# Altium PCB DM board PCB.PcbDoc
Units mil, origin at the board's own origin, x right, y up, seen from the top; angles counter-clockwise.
Board outline 3005.33 x 2700 mil, 4 copper layers (Top Layer, InternalPlane1, InternalPlane2, Bottom Layer); 39 components, 28 nets, 361 pads, 4 vias.
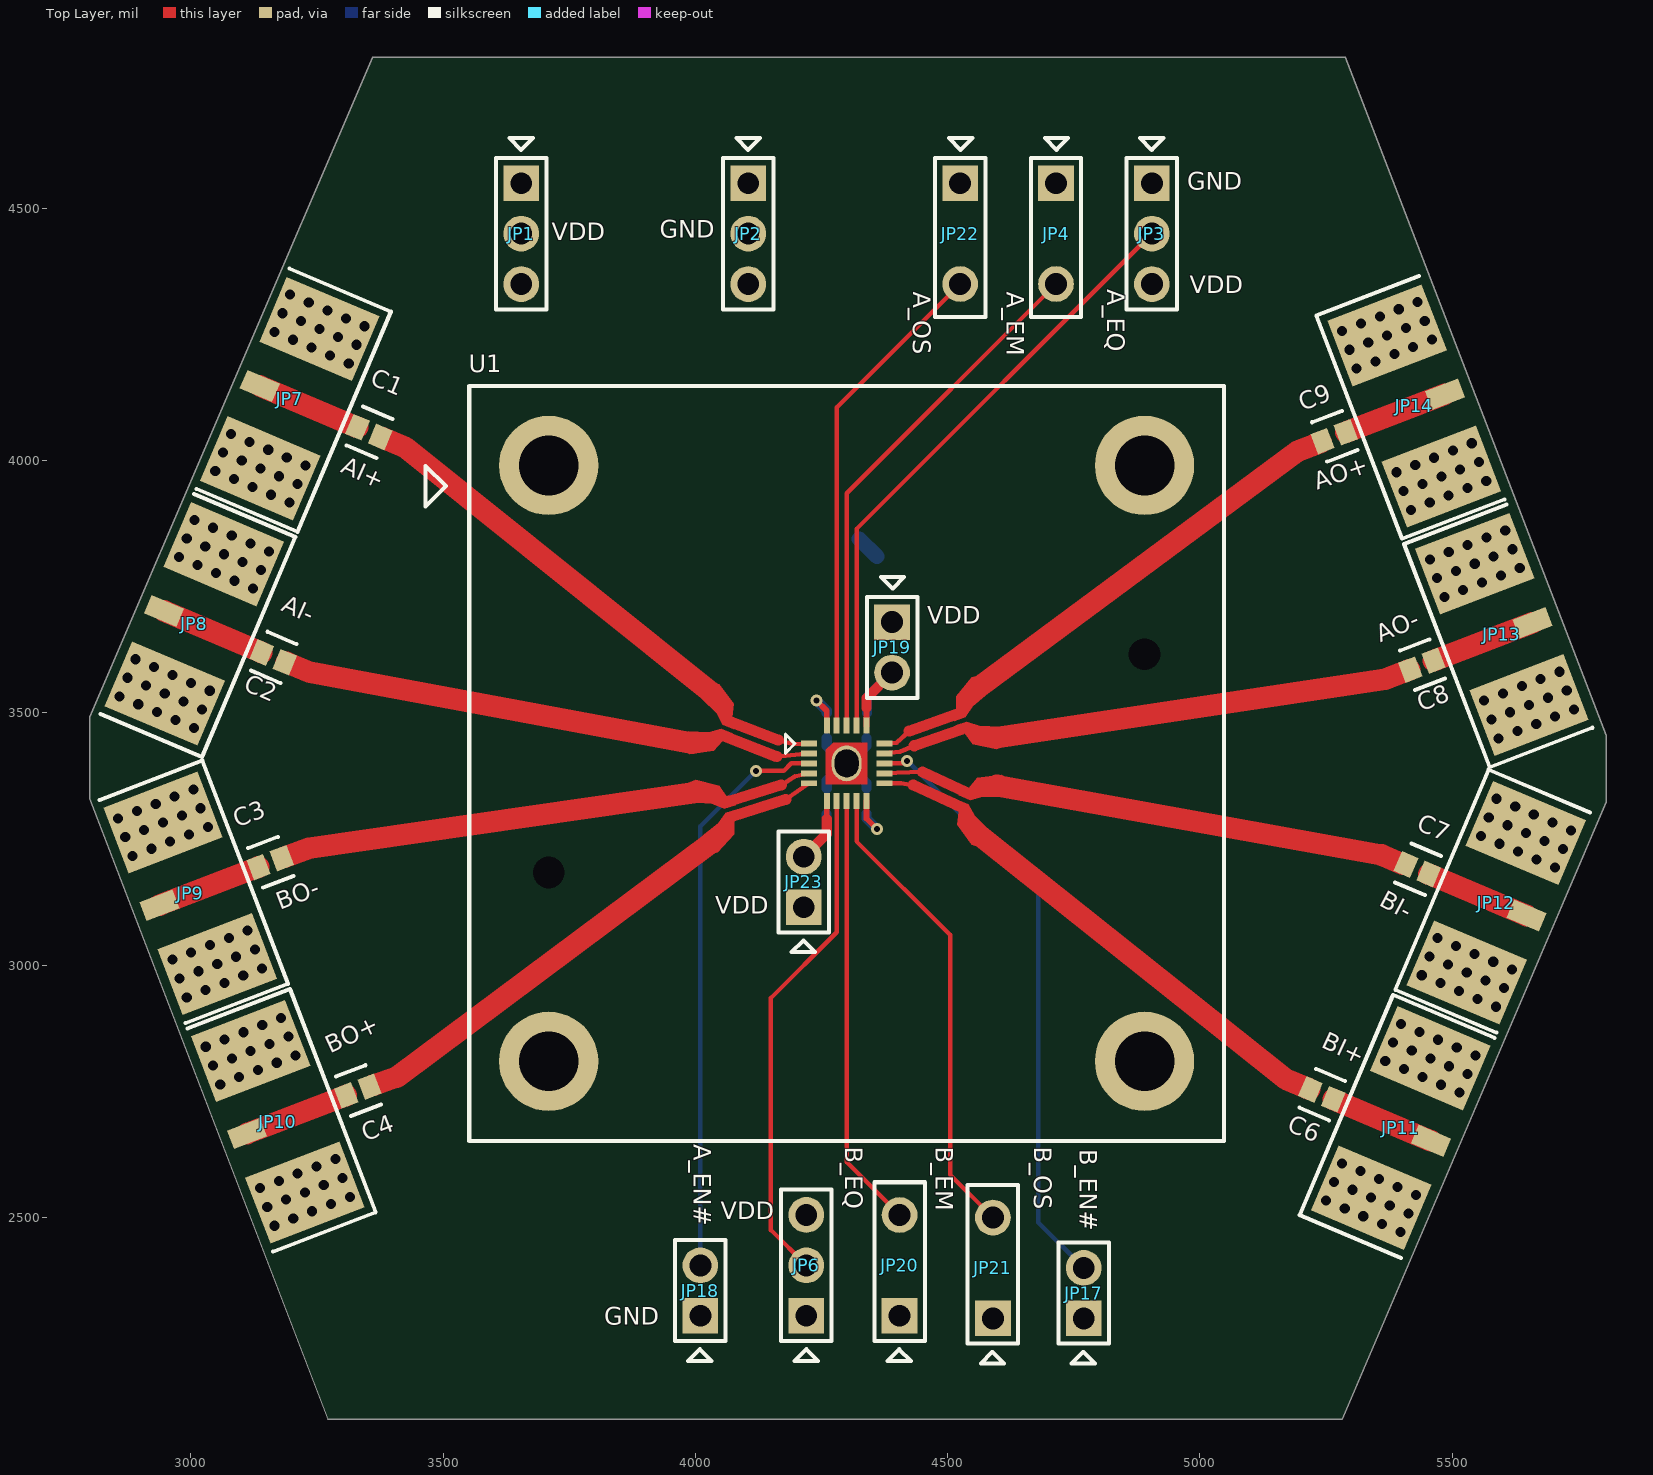
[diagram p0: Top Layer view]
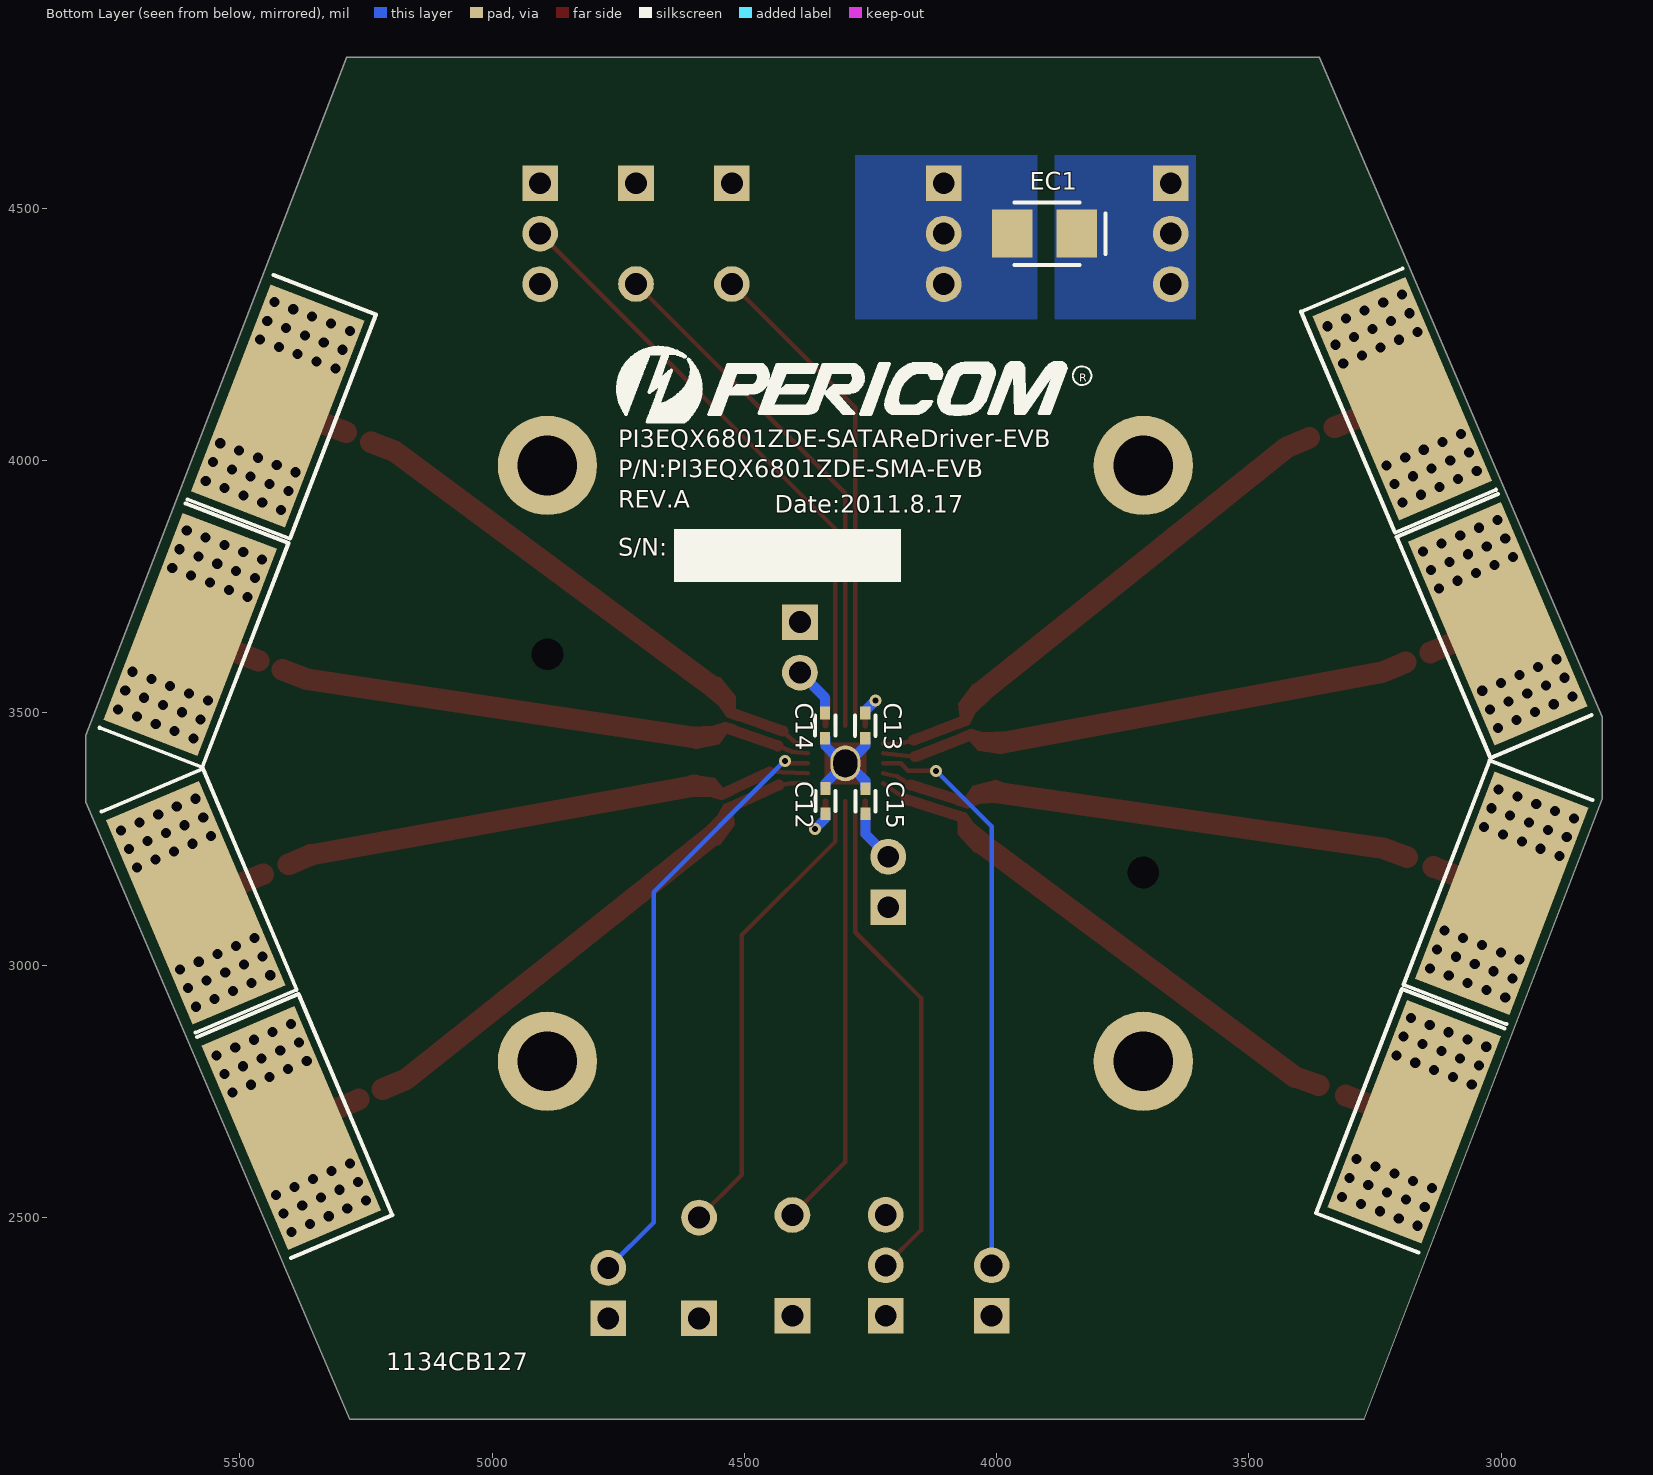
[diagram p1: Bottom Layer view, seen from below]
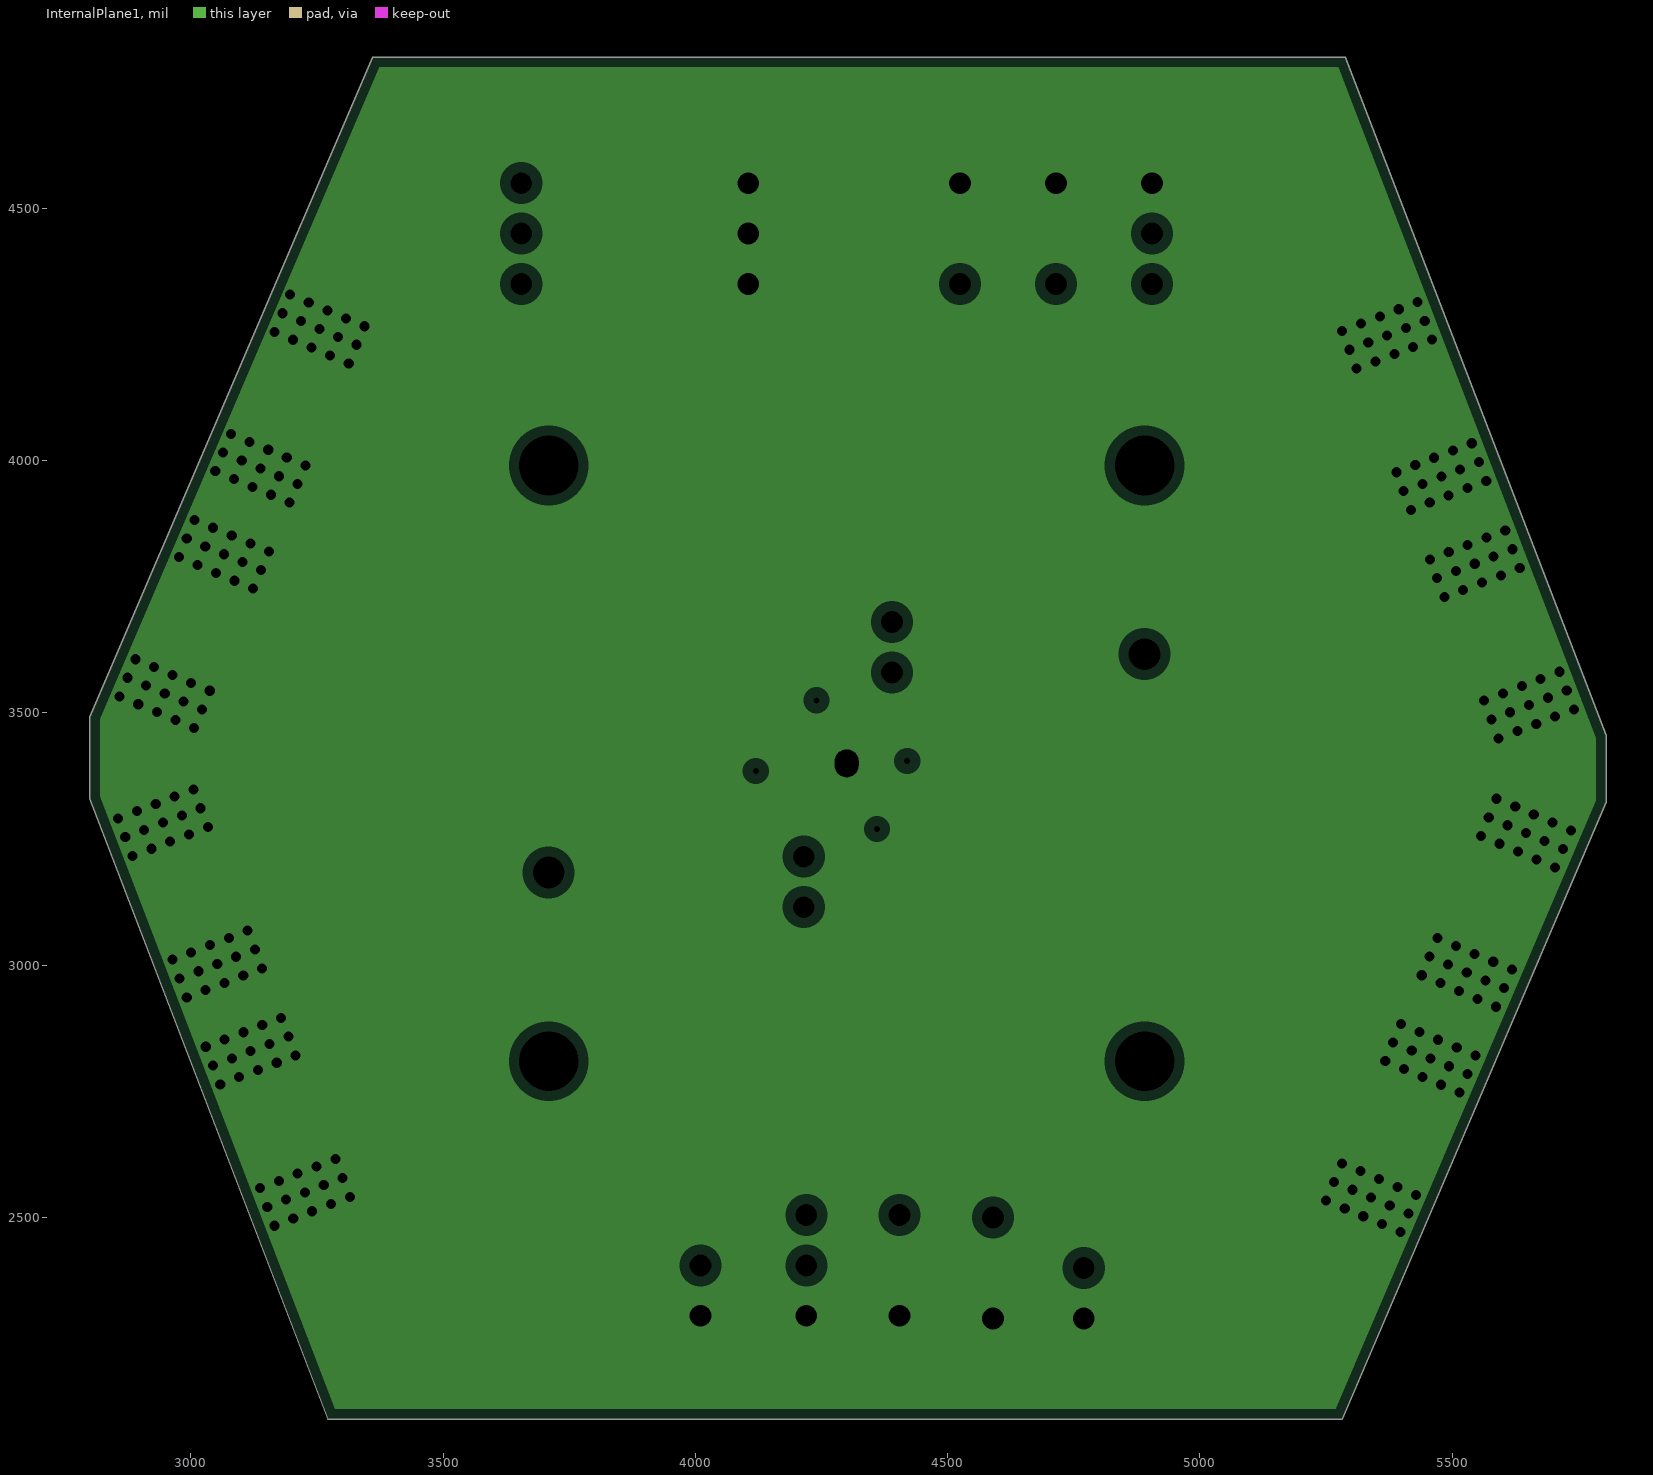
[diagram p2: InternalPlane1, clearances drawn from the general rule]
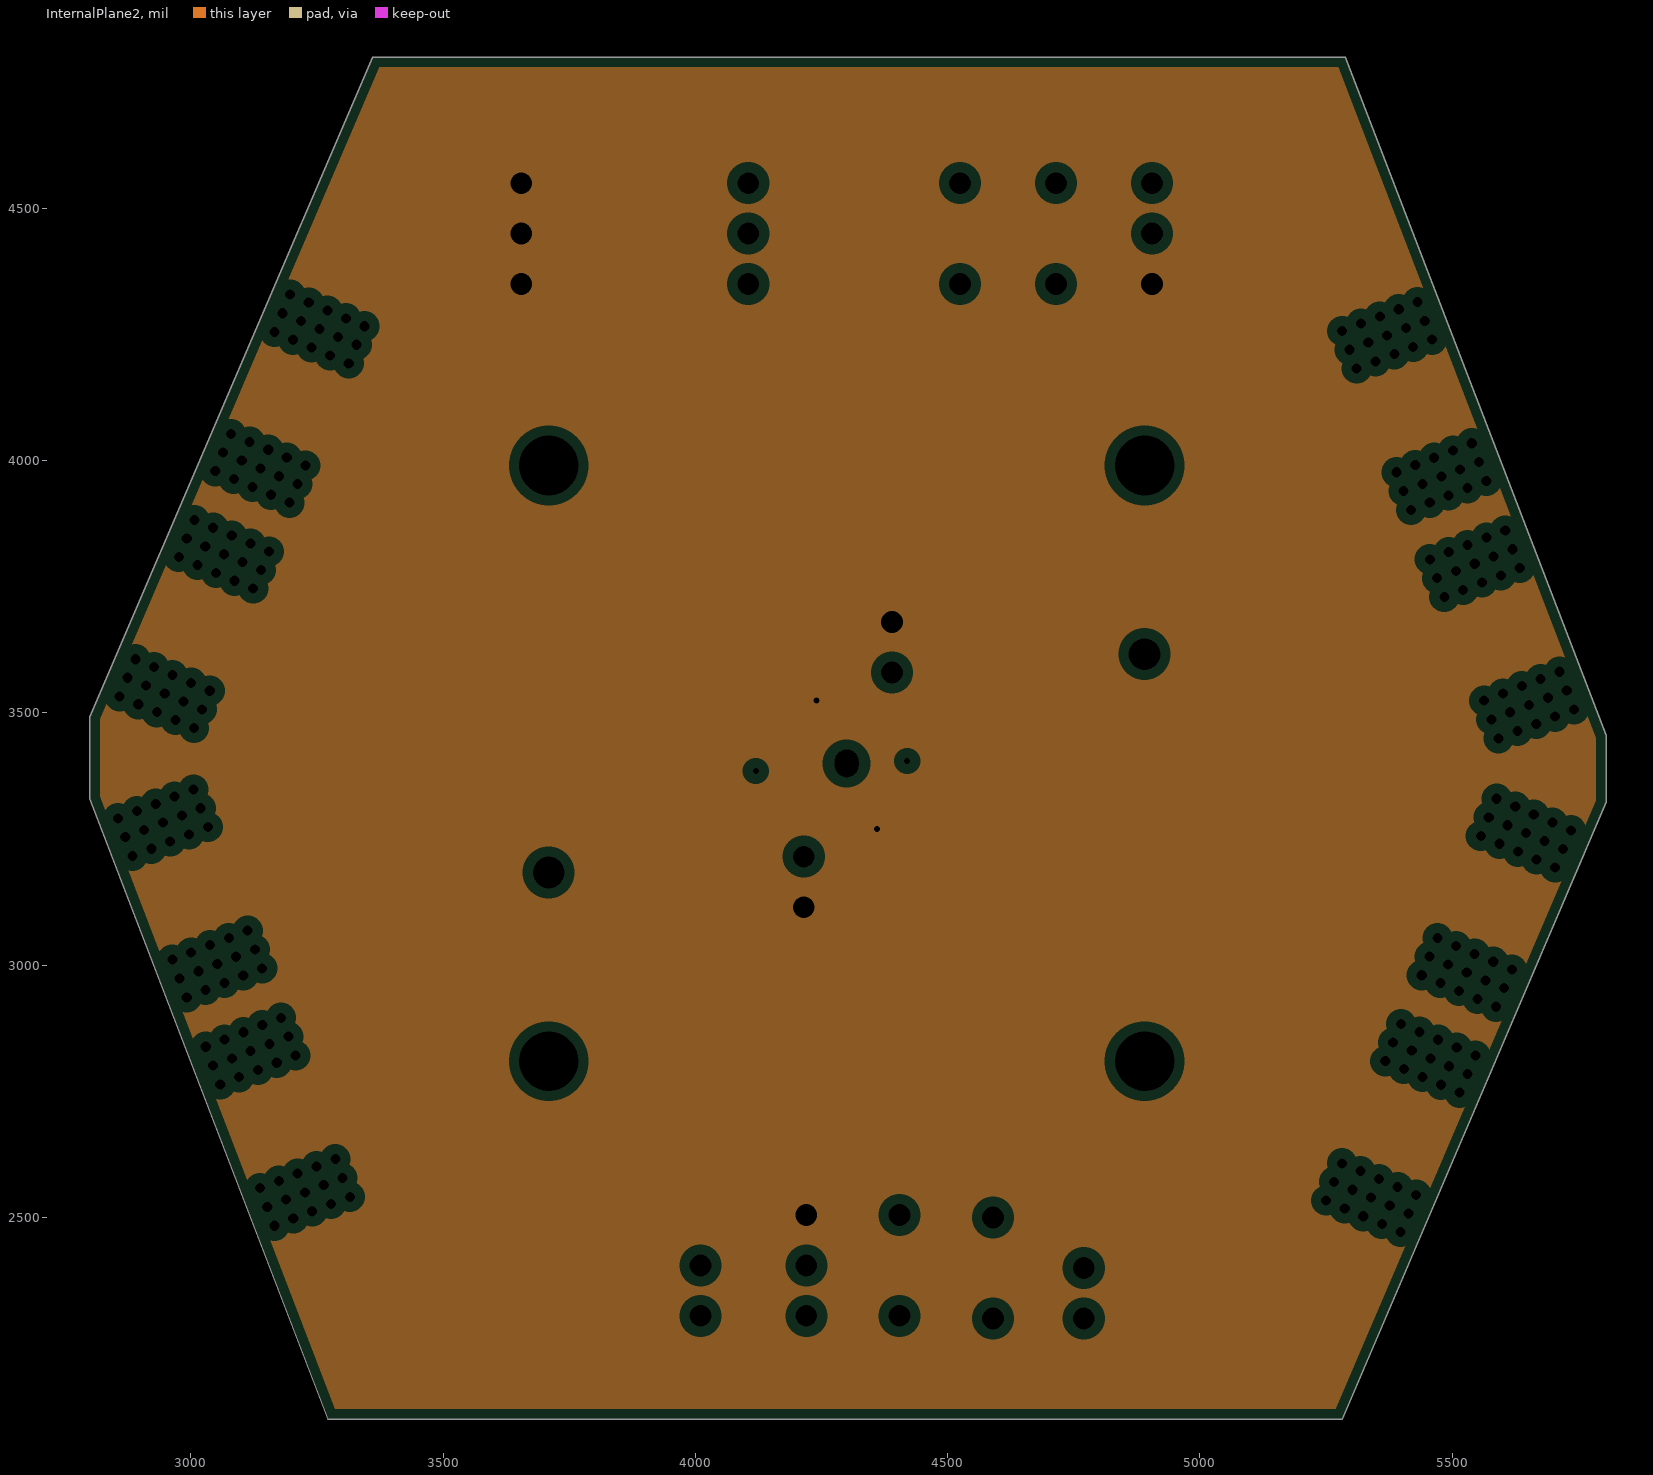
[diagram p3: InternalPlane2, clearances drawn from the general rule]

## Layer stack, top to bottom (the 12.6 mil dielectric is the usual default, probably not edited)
Top Layer: signal copper 1.4
Dielectric: core 12.6, FR-4, Dk 4.8
InternalPlane1: plane copper 1.4, net GND
Dielectric: prepreg 12.6, FR-4, Dk 4.8
InternalPlane2: plane copper 1.4, net VDD
Dielectric: core 12.6, FR-4, Dk 4.8
Bottom Layer: signal copper 1.4

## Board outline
3271.92,2100 2800,3329.81 2800,3491.67 3360.71,4800 5288.45,4800 5805.33,3455.12 5805.33,3323.7 5282.21,2100

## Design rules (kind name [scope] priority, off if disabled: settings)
Clearance [All] p1: gap=5
ComponentClearance [All] p1: gap=0 collisioncheckmode=3 verticalgap=0
HoleSize [All] p1: absolutevalues=TRUE maxlimit=500 minlimit=1 maxpercent=80.000 minpercent=20.000
PlaneClearance [All] p1: clearance=20
PlaneConnect [All] p1: planeconnectstyle=Direct reliefexpansion=20 reliefentries=4 reliefconductorwidth=10 reliefairgap=10
PolygonConnect [All] p1: connectstyle=Direct reliefconductorwidth=10 reliefentries=4 polygonreliefangle="90 Angle"
RoomDefinition "PI3EQX6801ZDE_SMA BOARD" [InComponentClass('PI3EQX6801ZDE_SMA BOARD')] p1: confinementstyle=ConfineIn formatcopy=TRUE lockcomponents=FALSE outline 0,0 10830,0 10830,5820 0,5820
RoutingVias [All] p1: holewidth=28 width=50 viastyle="Through Hole" minholewidth=8 minwidth=10 maxholewidth=28 maxwidth=50
SolderMaskExpansion [All] p1: expansion=4
TestPointUsage [All] p1: valid=0 allowmultiple=FALSE
Testpoint [All] p1: side=15 testpointundercomponent=TRUE minsize=40 maxsize=100 preferedsize=60 minholesize=0 maxholesize=40 preferedholesize=32 testpointgrid=1 style=1023 order=0123456789
Width [All] p1: maxlimit=150 minlimit=5 preferedwidth=10
15 further rules are at their usual default settings.

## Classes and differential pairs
component class "PI3EQX6801ZDE_SMA BOARD": C1 C2 C3 C4 C6 C7 C8 C9 C12 C13 C14 C15 EC1 JP1 JP2 JP3 JP4 JP6 JP7 JP8 JP9 JP10 JP11 JP12 JP13 JP14 JP17 JP18 JP19 JP20 JP21 JP22 JP23 U1

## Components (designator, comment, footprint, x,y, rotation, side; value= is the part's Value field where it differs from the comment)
C1 "0.1u_0306" CC_0306 3352.93,4056.51 r337 top
C2 "0.1u_0306" CC_0306 3163.43,3610.07 r337 top
C3 "0.1u_0306" CC_0306 3157.31,3203.34 r21 top
C4 "0.1u_0306" CC_0306 3331.12,2750.55 r21 top
C6 "0.1u_0306" CC_0306 5241.83,2743.73 r337 top
C7 "0.1u_0306" CC_0306 5431.33,3190.18 r337 top
C8 "0.1u_0306" CC_0306 5440.16,3594.82 r21 top
C9 "0.1u_0306" CC_0306 5266.35,4047.6 r21 top
C12 "0.1u_0402" CC_0402 4339.37,3325.2 r90 bottom
C13 "0.1u_0402" CC_0402 4260.63,3474.8 r270 bottom
C14 "0.1u_0402" CC_0402 4340,3475 r270 bottom
C15 "0.1u_0402" CC_0402 4260,3325 r270 bottom
EC1 "10u_3528" CT_3528 3905,4450 r0 bottom
JP1 "3x1 Pin Header" "3x1 Pin Header" 3655,4550 r270 top
JP2 "3x1 Pin Header" "3x1 Pin Header" 4105,4550 r270 top
JP3 "3x1 Pin Header" "3x1 Pin Header" 4905,4550 r270 top
JP4 "2x1_200 mil Pin Header" "2x1_200 mil Pin Header" 4715,4550 r270 top
JP6 "3x1 Pin Header" "3x1 Pin Header" 4220,2305 r90 top
JP7 "RF_SMA_End" RF_SMA_End 3288.5,4083.86 r337 top
JP8 "RF_SMA_End" RF_SMA_End 3098.99,3637.42 r337 top
JP9 "RF_SMA_End" RF_SMA_End 3091.96,3178.25 r21 top
JP10 "RF_SMA_End" RF_SMA_End 3265.77,2725.46 r21 top
JP11 "RF_SMA_End" RF_SMA_End 5306.26,2716.38 r157 top
JP12 "RF_SMA_End" RF_SMA_End 5495.77,3162.83 r157 top
JP13 "RF_SMA_End" RF_SMA_End 5505.51,3619.9 r201 top
JP14 "RF_SMA_End" RF_SMA_End 5331.7,4072.69 r201 top
JP17 "2x1 Pin Header" "2x1 Pin Header" 4770,2300 r90 top
JP18 "2x1 Pin Header" "2x1 Pin Header" 4010,2305 r90 top
JP19 "2x1 Pin Header" "2x1 Pin Header" 4390,3680 r270 top
JP20 "2x1_200 mil Pin Header" "2x1_200 mil Pin Header" 4405,2305 r90 top
JP21 "2x1_200 mil Pin Header" "2x1_200 mil Pin Header" 4590,2300 r90 top
JP22 "2x1_200 mil Pin Header" "2x1_200 mil Pin Header" 4525,4550 r270 top
JP23 "2x1 Pin Header" "2x1 Pin Header" 4215,3115 r90 top
U1 "PI3EQX6801ZDE@TQFN20" "TQFN20_4x4 SOCKET" 4300,3400 r0 top locked
? "" C100/F50_EDITA_V1 4528,3484 r289 top
? "" C100/F50_EDITA_V1 4534,3327 r247 top
? "" C100/F50_EDITA_V1 4068,3309 r107 top
? "" C100/F50_EDITA_V1 4062,3469 r67 top
? "" PSC_LOG 4645,4180 r180 bottom

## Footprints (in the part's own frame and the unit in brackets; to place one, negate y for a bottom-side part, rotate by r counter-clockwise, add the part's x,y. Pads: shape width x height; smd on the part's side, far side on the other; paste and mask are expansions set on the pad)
"2x1 Pin Header" [mm] "Pin Header 2x1 Pitch 2.54mm"
  rect 1.8x1.8 hole 1.1: 1(0,0)
  round 1.8 hole 1.1: 2(2.54,0)
  silkscreen extent -2.27,-1.27 3.81,1.27
"2x1_200 mil Pin Header" [mm]
  rect 1.8x1.8 hole 1.1: 1(0,0)
  round 1.8 hole 1.1: 2(5.075,0)
  silkscreen extent -2.27,-1.27 6.73,1.27
"3x1 Pin Header" [mm] "Pin Header 3x1 Pitch 2.54mm"
  rect 1.8x1.8 / inner round 1.8 / far side rect 1.8x1.8 hole 1.1: 1(0,0)
  round 1.8 hole 1.1: 2(2.54,0) 3(5.08,0)
  silkscreen extent -2.27,-1.27 6.35,1.27
C100/F50_EDITA_V1 [mil]
  Top Layer region: 74.23,68.36 35.23,68.36 20.51,30.23 4.5,9.63 4.5,-13.85 25.37,-13.85 25.37,-1.93 50.7,6.02 75.28,47.48
  Top Layer region: -74,68 -35,68 -20.27,29.87 -4.5,9.57 -4.5,-14.21 -25.14,-14.21 -25.14,-2.29 -50.47,5.65 -75.05,47.12
CC_0306 [mm]
  rect 0.9x1.092 smd: 1(-0.625,0) 2(0.625,0)
  silkscreen extent -0.78,-1.05 0.85,1.07
CC_0402 [mil]
  rect 25x20 smd: 1(-25,0) 2(25,0)
  silkscreen extent -20,-20 20,20
CT_3528 [mil]
  rect 80x95 smd: 1(-64,0) 2(64,0)
  silkscreen extent -121,-62 60,62
PSC_LOG [mil]
  silkscreen extent -107,-103 833,45
RF_SMA_End [mil] "PSF-S01B-2_FR4"
  rect 70x40 smd: 1(-165,0)
  rect 200x140 smd: 2(-100,-150) 3(-100,150)
  round 25 / inner round 35 / far side round 25 hole 20: 20(-180.02,190) 20(-180,150) 20(-180,-150) 20(-180,110) 20(-180,-190) 20(-180,-110) 20(-180,-110) 20(-140,190) 20(-140,-110) 20(-140,-190) 20(-140,150) 20(-140,-150) 20(-140,110) 20(-100,-190) 20(-100,-150) 20(-100,190) 20(-100,-110) 20(-100,150) 20(-100,110) 20(-60,110) 20(-60,190) 20(-60,-150) 20(-60,-190) 20(-60,150) 20(-60,-110) 20(-20,-190) 20(-20,110) 20(-20,150) 20(-20,-110) 20(-20,-150) 20(-20,190)
  rect 200x440 smd far side: 34(-100,0)
  silkscreen extent -201,-237 17,237
"TQFN20_4x4 SOCKET" [mm]
  rect 0.8x0.3 smd: 1(-1.9,1) 2(-1.9,0.5) 3(-1.9,0) 4(-1.9,-0.5) 5(-1.9,-1) 11(1.9,-1) 12(1.9,-0.5) 13(1.9,0) 14(1.9,0.5) 15(1.9,1)
  rect 0.3x0.8 smd: 6(-1,-1.9) 7(-0.5,-1.9) 8(0,-1.9) 9(0.5,-1.9) 10(1,-1.9) 16(1,1.9) 17(0.5,1.9) 18(0,1.9) 19(-0.5,1.9) 20(-1,1.9)
  oval 1.5x1.8 hole 1.2 slot 1.4 at 90 deg: 21(0,0)
  round 5 hole 3: ""(-15,-15) ""(-15,15) ""(15,-15) ""(15,15)
  round 0 hole 1.6 unplated: ""(-15,-5.5) ""(15,5.5)
  Top Layer region: 1.05,-1.05 1.05,1.05 -0.68,1.05 -1.05,0.68 -1.05,-1.05
  silkscreen extent -21.19,-19 19,19

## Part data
C1 C2 C3 C4 C6 C7 C8 C9: library part C_0.1u_0306
C12 C13 C15: library part C_0.1u_0402
C14: library part C_0.1u_0402_Dup1
EC1: library part C_tan_22u_3528
JP1 JP2: library part "3x1 Pin Header_Dup1"
JP4 JP20 JP21 JP22: library part "3x1 Pin Header"
JP19 JP23: library part "2x1 Pin Header_Dup1"
U1: library part PI2EQX6811ZDE@TQFN20

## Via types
v1: diameter 24, hole 12, Top Layer to Bottom Layer, tented both sides, 4 vias

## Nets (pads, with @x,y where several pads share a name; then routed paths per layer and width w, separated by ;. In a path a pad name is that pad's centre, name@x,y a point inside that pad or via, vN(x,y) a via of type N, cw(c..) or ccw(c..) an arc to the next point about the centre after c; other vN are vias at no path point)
A_EM: JP4.2 U1.18 | length 1047.3
  Top Layer w9: U1.18 4300,3935.2 JP4.2
A_EN#: JP18.2 U1.3 | length 1137
  Top Layer w9: v1(4120,3385) 4175,3385 4190,3400 U1.3
  Bottom Layer w9: JP18.2 4010,3275 v1(4120,3385)
A_EQ: JP3.2 U1.17 | length 1217.6
  Top Layer w9: U1.17 4319.69,3864.68 JP3.2
A_OS: JP22.2 U1.19 | length 976.7
  Top Layer w9: U1.19 4280.31,4105.51 JP22.2
B_EM: JP20.2 U1.8 | length 863.9
  Top Layer w9: U1.8 4300,2609.8 JP20.2
B_EN#: JP17.2 U1.13 | length 1197.2
  Top Layer w9: U1.13 4415,3400 v1(4420,3405)
  Bottom Layer w9: v1(4420,3405) 4680,3145 4680,2490 JP17.2
B_EQ: JP6.2 U1.7 | length 1003.2
  Top Layer w9: JP6.2 4150,2475 4150,2935 4280.31,3065.32 U1.7
B_OS: JP21.2 U1.9 | length 937.4
  Top Layer w9: U1.9 4319.69,3245.32 4505,3060 4505,2584.8 JP21.2
GND: C12.2 C13.2 C14.2 C15.1 EC1.2 JP2.1 JP2.2 JP2.3 JP3.1 JP4.1 JP6.1 JP7.2 JP7.3 JP7.20 JP7.34 JP8.2 JP8.3 JP8.20 JP8.34 JP9.2 JP9.3 JP9.20 JP9.34 JP10.2 JP10.3 JP10.20 JP10.34 JP11.2 JP11.3 JP11.20 JP11.34 JP12.2 JP12.3 JP12.20 JP12.34 JP13.2 JP13.3 JP13.20 JP13.34 JP14.2 JP14.3 JP14.20 JP14.34 JP17.1 JP18.1 JP20.1 JP21.1 JP22.1 U1.21 | length 173.4
  Bottom Layer w20: C15.1@4260.63,3350.2 4260.63,3365.63 U1.21@4280,3385 ; C13.2 4260.63,3434.37 U1.21@4280,3415 ; U1.21@4315,3410 4339.37,3434.37 C14.2@4339.37,3449.8 ; U1.21@4320,3380 4339.37,3360.63 C12.2
NetC1_1: C1.1 JP7.1 | length 210.4
  Top Layer w43: JP7.1 C1.1
NetC1_2: C1.2 U1.1 | length 993.5
  Top Layer w9: 4165,3446 4195,3438 U1.1
  Top Layer w22: 4069.17,3482.46 4165,3446
  Top Layer w43: C1.2@3380.65,4045.39 3425.81,4025.9 4035,3538
NetC2_1: C2.1 JP8.1 | length 210.4
  Top Layer w43: JP8.1 C2.1
NetC2_2: C2.2 U1.2 | length 996.4
  Top Layer w9: 4161.6,3413.42 U1.2
  Top Layer w22: 4058,3454 4161.6,3413.42
  Top Layer w43: C2.2@3189.76,3600.3 3236.7,3580.37 3994,3440
NetC3_1: C3.1 JP9.1 | length 210.4
  Top Layer w43: JP9.1 C3.1
NetC3_2: C3.2 U1.4 | length 998
  Top Layer w9: 4170.8,3357.44 4197,3374 U1.4
  Top Layer w22: 4067,3325 4170.8,3357.44
  Top Layer w43: C3.2@3185.97,3213.82 3233.97,3232.07 4004,3343
NetC4_1: C4.1 JP10.1 | length 210.4
  Top Layer w43: JP10.1 C4.1
NetC4_2: C4.2 U1.5 | length 996.2
  Top Layer w9: 4179.7,3328.82 U1.5
  Top Layer w22: 4074,3295 4179.7,3328.82
  Top Layer w43: C4.2@3361.97,2761.82 3408.13,2778.35 4034,3245
NetC6_1: C6.1 U1.11 | length 994.3
  Top Layer w9: U1.11 4408,3361 4432,3357
  Top Layer w22: 4432,3357 4526.3,3313.48
  Top Layer w43: 4559,3261 5171.63,2773.68 C6.1@5217.76,2754.1
NetC6_2: C6.2 JP11.1 | length 210.4
  Top Layer w43: C6.2 JP11.1
NetC7_1: C7.1 U1.12 | length 991.9
  Top Layer w9: U1.12 4450,3383
  Top Layer w22: 4450,3383 4536,3343
  Top Layer w43: 4598,3356 5360.36,3218.28 C7.1@5403.7,3199.88
NetC7_2: C7.2 JP12.1 | length 210.4
  Top Layer w43: C7.2 JP12.1
NetC8_1: C8.1 U1.14 | length 994.4
  Top Layer w9: U1.14 4406,3423 4434,3435
  Top Layer w22: 4434,3435 4529,3468
  Top Layer w43: 4596,3451 5367.12,3566.77 C8.1@5415.88,3585.49
NetC8_2: C8.2 JP13.1 | length 210.4
  Top Layer w43: C8.2 JP13.1
NetC9_1: C9.1 U1.15 | length 992.3
  Top Layer w9: U1.15 4399,3441 4424,3464
  Top Layer w22: 4424,3464 4518,3497
  Top Layer w43: 4563,3552 5193.67,4018.63 C9.1@5240.27,4036.51
NetC9_2: C9.2 JP14.1 | length 210.4
  Top Layer w43: C9.2 JP14.1
NetC14_1: C14.1 JP19.2 U1.16 | length 226.9
  Top Layer w11: U1.16 4339.37,3510
  Top Layer w20: 4339.37,3510 4339.37,3529.37 JP19.2
  Bottom Layer w20: C14.1 4340,3530 JP19.2
NetC15_2: C15.2 JP23.2 U1.6 | length 232.7
  Top Layer w11: 4260.63,3290 U1.6
  Top Layer w20: JP23.2 4260.63,3260.63 4260.63,3290
  Bottom Layer w20: JP23.2 4260,3260 C15.2
VDD: C12.1 C13.1 EC1.1 JP1.1 JP1.2 JP1.3 JP3.3 JP6.3 JP19.1 JP23.1 U1.10 U1.20 | length 195
  Top Layer w11: v1(4240,3525) 4260.63,3504.37 U1.20 ; U1.10 4339.37,3290.63 v1(4360,3270)
  Bottom Layer w20: v1(4240,3525) 4260.63,3504.37 C13.1 ; C12.1 4339.37,3290.63 v1(4360,3270)
pads on no net: U1.
copper on no net: | length 49.5
  Bottom Layer w30: 4325,3845 4360,3810

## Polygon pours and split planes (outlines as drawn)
VDD on Bottom Layer "MidLayer1-No Net" (solid, remove dead copper, pour order 1001): 3605,4605 3885,4605 3885,4280 3605,4280 3605,4605
GND on Bottom Layer "MidLayer1-No Net" (solid, remove dead copper, pour order 1000): 3920,4605 4280,4605 4280,4280 3920,4280 3920,4605
no net on Top Solder "MidLayer1-No Net" (solid): 5225,4290 5570,3395 5195,2510 4600,2900 3900,2900 3370,2510 3025,3410 3400,4295 3900,3900 4700,3900 5225,4290
GND on InternalPlane1 (split plane): 5784.93,3451.34 5784.93,3327.87 5268.75,2120.39 3285.94,2120.39 2820.39,3333.59 2820.39,3487.48 3374.16,4779.61 5274.44,4779.61
VDD on InternalPlane2 (split plane): 5784.93,3451.34 5784.93,3327.87 5268.75,2120.39 3285.94,2120.39 2820.39,3333.59 2820.39,3487.48 3374.16,4779.61 5274.44,4779.61

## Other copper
Top Layer:
  text "TOP LAYER" at 7304,2271.5 h80
  text "1" at 7692,2141.5 h80
Bottom Layer:
  text "BOTTOM LAYER" at 7304,2271.5 h80
  text "4" at 7692,2141.5 h80

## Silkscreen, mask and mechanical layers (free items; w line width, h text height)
Top Overlay:
  text "GND" at 4975,4525 h60
  text "GND" at 3930,4430 h60
  text "VDD" at 3715,4425 h60
  text "A_EQ" at 4805,4340 h60 r270
  text "A_OS" at 4420,4335 h60 r270
  text "A_EM" at 4605,4335 h60 r270
  text "VDD" at 4980,4320 h60
  text "AI+" at 3290,3967 h60 r336
  text "AO+" at 5237,3931 h60 r19
  text "AI-" at 3172,3693 h60 r336
  text "VDD" at 4460,3665 h60
  text "AO-" at 5363,3628 h60 r23
  text "BI-" at 5348,3109 h60 r332
  text "BO-" at 3181,3098 h60 r21
  text "VDD" at 4040,3090 h60
  text "BI+" at 5234,2827 h60 r335
  text "BO+" at 3281,2814 h60 r25
  text "A_EN#" at 3985,2645 h60 r270
  text "B_EQ" at 4285,2640 h60 r270
  text "B_EM" at 4465,2640 h60 r270
  text "B_OS" at 4660,2640 h60 r270
  text "B_EN#" at 4750,2635 h60 r270
  text "VDD" at 4050,2485 h60
  text "GND" at 3820,2275 h60
  text "TOP SILKSCREEN LAYER" at 7304,2271.5 h80
  text "5" at 7692,2141.5 h80
Bottom Overlay:
  rectangle: 4190,3760 4640,3865
  text "PI3EQX6801ZDE-SATAReDriver-EVB" at 4750,4015 h60
  text "P/N:PI3EQX6801ZDE-SMA-EVB" at 4750,3955 h60
  text "REV.A" at 4750,3895 h60
  text "Date:2011.8.17" at 4440,3885 h60
  text "S/N:" at 4750,3800 h60
  text "BOTTOM SILKSCREEN LAYER" at 7304,2271.5 h80
  text "1134CB127" at 5210,2185 h60
  text "6" at 7692,2141.5 h80
Top Paste:
  text "TOP PASTE LAYER" at 7304,2271.5 h80
  text "TOP PASTE LAYER" at 7304,2271.5 h80
  text "TP" at 7672,2141.5 h80
Bottom Paste:
  text "BOTTOM PASTE LAYER" at 7304,2271.5 h80
  text "BOTTOM PASTE LAYER" at 7304,2271.5 h80
  text "BP" at 7672,2141.5 h80
Top Solder:
  pour cut-out: 4450,3710 4575,3710 4575,3660 4450,3660
  pour cut-out: 4030,3135 4155,3135 4155,3085 4030,3085
  pour cut-out: 5221,3970 5326,4008 5345,3953 5238,3916
  pour cut-out: 5339,3672 5444,3710 5463,3655 5356,3618
  pour cut-out: 5345.16,3162.2 5446.28,3114.83 5420.82,3062.5 5319,3112
  pour cut-out: 5232.16,2882.2 5333.28,2834.83 5307.82,2782.5 5206,2832
  pour cut-out: 3252.36,2855.31 3353.65,2902.32 3377.37,2849.18 3274,2803
  pour cut-out: 3148.36,3132.31 3249.65,3179.32 3273.37,3126.18 3170,3080
  pour cut-out: 3176.04,3744.74 3276.31,3695.61 3249.94,3643.73 3149,3695
  pour cut-out: 3297.04,4017.74 3397.31,3968.61 3370.94,3916.73 3270,3968
  pour cut-out: 4190,3285 4190,3540 4410,3540 4410,3285
  lines w50: 2950,3125 3135,3195 ; 2950,3700 3150,3615 ; 3120,2670 3305,2740 ; 3145,4145 3335,4065 ; 5255,2740 5450,2655 ; 5285,4055 5470,4125 ; 5450,3185 5635,3100 ; 5465,3605 5650,3675
  text "TOP SOLDER LAYER" at 7304,2271.5 h80
  text "7" at 7692,2141.5 h80
Bottom Solder:
  text "BOTTOM SOLDER LAYER" at 7304,2271.5 h80
  text "8" at 7692,2141.5 h80
Drill Guide:
  text "DRILL GUIDE LAYER" at 7304,2271.5 h80
  text "10" at 7672,2141.5 h80
Mechanical 1:
  lines w8: 2800,3329.81 3271.92,2100 5282.21,2100 5805.33,3323.7 5805.33,3455.12 5288.45,4800 3360.71,4800 2800,3491.67 2800,3329.81
  lines w10: 7012,2231.5 7012,2621.5 ; 7412,2101.5 7412,2231.5 ; 7412,2361.5 7412,2491.5 ; 7942,2361.5 7942,2491.5
  lines w12: 6492,2231.5 8870,2231.5 ; 6492,2361.5 8870,2361.5 ; 6492,2491.5 8870,2491.5 ; 6492,2621.5 8870,2621.5 ; 6492,2681.5 6942,2681.5 ; 6492,2731.5 6852,2731.5 ; 6492,2781.5 6942,2781.5 ; 8032,2681.5 8870,2681.5 ; 8032,2781.5 8870,2781.5 ; 8122,2731.5 8870,2730.5
  lines w15: 6492,2101.5 8870,2101.5 8870,2851.5 6492,2851.5 6492,2101.5
  text "Pericom" at 7172,2681.5 h180
  text "PCB NAME" at 6532,2531.5 h60
  text "PI3EQX6801STBZDE SMA BOARD" at 7042,2531.5 h80
  text "REV.A" at 8516,2531.5 h80
  text "DATE" at 6622,2401.5 h60
  text "8/17/2011" at 7032,2401.5 h80
  text "Drawn by" at 7442,2401.5 h60
  text "Haojie Ci" at 7992,2401.5 h80
  text "TITLE" at 6602,2271.5 h60
  text "SHEET NUMBER" at 6612,2141.5 h60
  text "OF       10" at 7912,2141.5 h80
Drill Drawing:
  lines w10: 6642,3831.5 6642,4321.5 ; 6722,3201.5 6932,3201.5 ; 6722,3541.5 6932,3541.5 ; 6802,3261.5 6822,3201.5 ; 6802,3481.5 6822,3541.5 ; 6822,3311.5 6822,3201.5 ; 6822,3431.5 6822,3541.5 ; 6842,3261.5 6822,3201.5 ; 6842,3481.5 6822,3541.5 ; 7032,3831.5 7032,4321.5 ; 7942,3831.5 7942,4321.5 ; 9082,3831.5 9082,4321.5 ; 7022,3201.5 7022,3251.5 8062,3251.5 8062,3201.5 7022,3201.5 ; 7022,3292.5 7022,3342.5 8062,3342.5 8062,3292.5 7022,3292.5 ; 7022,3392.5 7022,3442.5 8062,3442.5 8062,3392.5 7022,3392.5 ; 7022,3491.5 8062,3491.5 8062,3541.5 7022,3541.5 7022,3491.5
  lines w12: 6162,3961.5 9682,3961.5 ; 6162,4091.5 9682,4091.5
  lines w15: 6162,3831.5 6162,4321.5 9682,4321.5 9682,3831.5 6162,3831.5
  text "IMPEDANCE CHART" at 6162,4351.5 h100
  text "TRACE" at 6712,4211.5 h60
  text "SINGLE-ENDED" at 7062,4211.5 h60
  text "DIFFERENTIAL-ENDED" at 8002,4211.5 h60
  text "LAYER(S)" at 6202,4171.5 h60
  text "TOLERANCE" at 9122,4171.5 h60
  text "TYPE" at 6712,4131.5 h60
  text "IMPEDANCE REQ'D" at 7062,4131.5 h60
  text "IMPEDANCE REQ'D" at 8002,4131.5 h60
  text "+/- 10%" at 9262,4011.5 h80
  text "1" at 6392,4001.5 h80
  text "--" at 7473,4002.5 h80
  text "100 ohm" at 8348,4002.5 h80
  text "22/10/22mil" at 6654,3996 h80
  text "50 ohm" at 7363,3875.5 h80
  text "--" at 8468,3874.5 h80
  text "1" at 6392,3871.5 h80
  text "+/- 10%" at 9262,3871.5 h80
  text "43 mil" at 6725,3863.5 h80
  text "LAYER1 SIGNAL" at 8103,3492.5 h80
  text "LAYER2 GND PLANE" at 8103,3392.5 h80
  text "THICKNESS is 1.6mm" at 6023,3352.5 h80
  text "LAYER3 POWER PLANE" at 8103,3292.5 h80
  text "LAYER4 SIGNAL" at 8103,3202.5 h80
  text "DRILL DRAWING LAYER" at 7304,2271.5 h80
  text "9" at 7692,2141.5 h80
